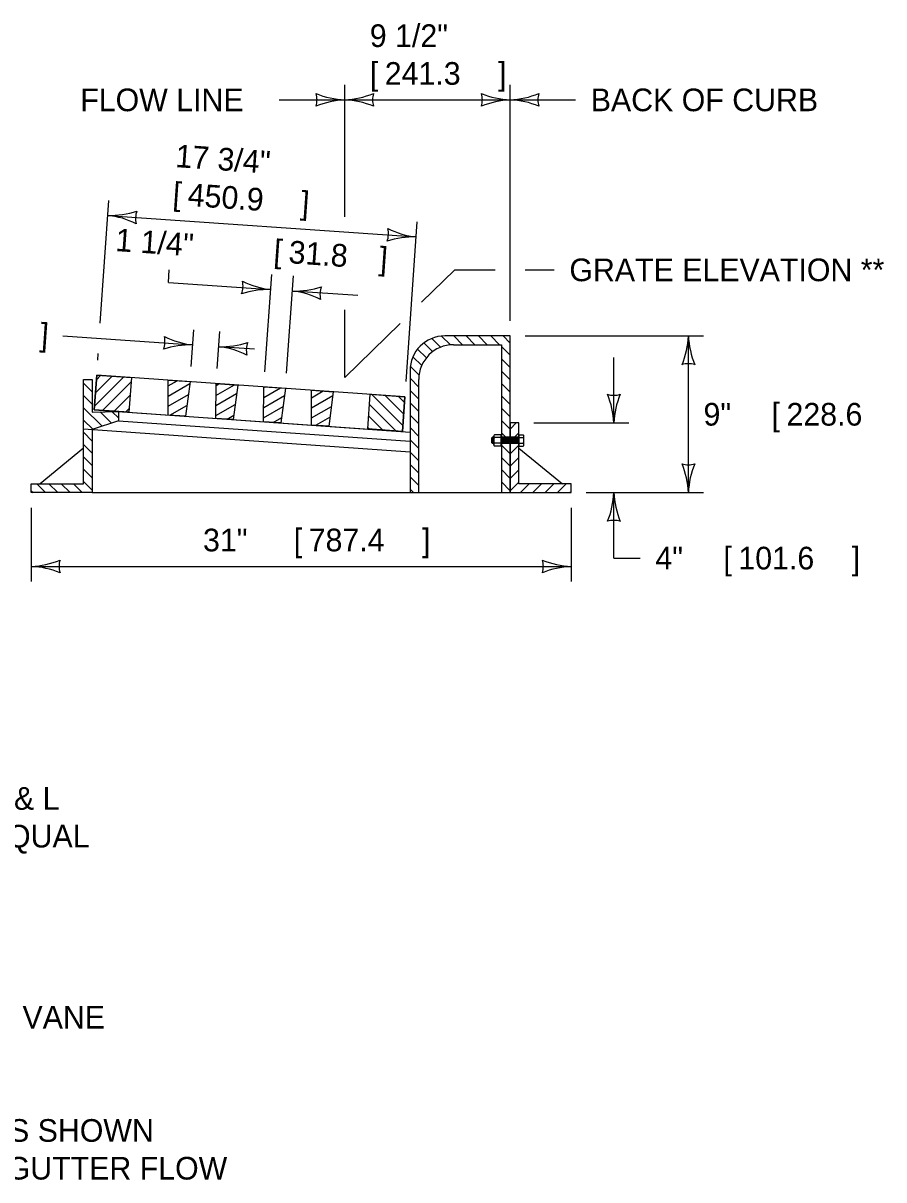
# Model space of a CAD drawing. Extents: x 49991.4 to 50057, y 49987.6 to 50011.4.
# Drawn here: x 50051.205 to 50053.484, y 49989.217 to 49992.28 of the extents above; entities that cross this region are included whole.
import ezdxf

# ---------------------------------------------------------------- set-up
doc = ezdxf.new("R2010")
doc.units = 0
for name, color, linetype in [('Level 1', 7, 'Continuous'), ('Level 2', 7, 'Continuous'), ('Level 3', 7, 'Continuous'), ('Level 4', 7, 'Continuous')]:
    doc.layers.add(name, color=color, linetype=linetype)

msp = doc.modelspace()

# ---------------------------------------------------------------- linework, layer by layer
at = {"layer": 'Level 1'}
for p, q in [((50052.2662, 49991.4332), (50052.2892, 49991.4101)), ((50052.287, 49991.4449), (50052.31, 49991.4219)), ((50052.3132, 49991.4513), (50052.3363, 49991.4282)), ((50052.3454, 49991.4517), (50052.3685, 49991.4286)), ((50052.378, 49991.4517), (50052.4011, 49991.4286)), ((50052.4106, 49991.4517), (50052.4337, 49991.4286)), ((50052.4432, 49991.4517), (50052.4663, 49991.4286)), ((50052.4714, 49991.4235), (50052.4945, 49991.4004)), ((50052.4758, 49991.4517), (50052.4945, 49991.433)), ((50052.2373, 49991.3968), (50052.2604, 49991.3738)), ((50052.2496, 49991.4171), (50052.2727, 49991.3941)), ((50052.2302, 49991.3714), (50052.2532, 49991.3483)), ((50052.4714, 49991.3909), (50052.4945, 49991.3678)), ((50051.4, 49991.348), (50051.3935, 49991.256)), ((50051.3942, 49991.2657), (50051.4715, 49991.343)), ((50051.3967, 49991.3008), (50051.441, 49991.3451)), ((50051.3991, 49991.3358), (50051.4105, 49991.3472)), ((50052.2161, 49991.2909), (50051.4, 49991.348)), ((50051.5895, 49991.3193), (50051.6134, 49991.333)), ((50052.2294, 49991.3395), (50052.2525, 49991.3165)), ((50052.4714, 49991.3583), (50052.4945, 49991.3353)), ((50051.3652, 49991.3269), (50051.3882, 49991.3039)), ((50051.4155, 49991.2544), (50051.4911, 49991.33)), ((50051.5893, 49991.2925), (50051.6464, 49991.3255)), ((50051.7158, 49991.2942), (50051.7648, 49991.3224)), ((50051.716, 49991.3209), (50051.7237, 49991.3253)), ((50051.8423, 49991.2885), (50051.8864, 49991.3139)), ((50051.8425, 49991.3152), (50051.8452, 49991.3168)), ((50051.9688, 49991.288), (50051.9999, 49991.306)), ((50052.2294, 49991.307), (50052.2525, 49991.2839)), ((50052.4714, 49991.3257), (50052.4945, 49991.3027)), ((50051.3652, 49991.2943), (50051.3882, 49991.2713)), ((50051.446, 49991.2523), (50051.4887, 49991.295)), ((50051.5891, 49991.2658), (50051.6426, 49991.2967)), ((50051.7154, 49991.2407), (50051.7667, 49991.2703)), ((50051.7156, 49991.2675), (50051.7705, 49991.2992)), ((50051.8421, 49991.2618), (50051.8974, 49991.2937)), ((50051.9686, 49991.2613), (50052.0251, 49991.2939)), ((50052.1222, 49991.2701), (50052.1922, 49991.2001)), ((50052.1278, 49991.2971), (50052.2107, 49991.2142)), ((50052.1629, 49991.2946), (50052.2129, 49991.2446)), ((50052.1979, 49991.2922), (50052.215, 49991.2751)), ((50052.2097, 49991.1987), (50052.2161, 49991.2909)), ((50052.2294, 49991.2744), (50052.2525, 49991.2513)), ((50052.4714, 49991.2931), (50052.4945, 49991.2701)), ((50051.3652, 49991.2617), (50051.4143, 49991.2126)), ((50051.3935, 49991.256), (50052.2097, 49991.1989)), ((50051.4091, 49991.2504), (50051.4388, 49991.2208)), ((50051.4411, 49991.251), (50051.4574, 49991.2347)), ((50051.4574, 49991.2513), (50051.4574, 49991.2513)), ((50051.4574, 49991.2513), (50052.2294, 49991.1972)), ((50051.4764, 49991.2502), (50051.4862, 49991.2599)), ((50051.5939, 49991.242), (50051.6388, 49991.2679)), ((50051.7453, 49991.2314), (50051.7629, 49991.2415)), ((50051.8419, 49991.2351), (50051.8936, 49991.2649)), ((50051.9684, 49991.2346), (50052.0212, 49991.2651)), ((50052.1201, 49991.2396), (50052.1572, 49991.2025)), ((50052.2294, 49991.2418), (50052.2525, 49991.2187)), ((50052.4714, 49991.2605), (50052.4945, 49991.2375)), ((50051.3652, 49991.2291), (50051.3899, 49991.2045)), ((50051.4574, 49991.227), (50052.2294, 49991.173)), ((50051.5136, 49991.2229), (50051.5136, 49991.2229)), ((50051.8669, 49991.2229), (50051.8898, 49991.2361)), ((50051.9805, 49991.215), (50052.0174, 49991.2363)), ((50052.118, 49991.2091), (50052.1221, 49991.205)), ((50052.2294, 49991.2092), (50052.2522, 49991.1864)), ((50052.4714, 49991.2279), (50052.4945, 49991.2049)), ((50052.4945, 49991.2048), (50052.5108, 49991.2212)), ((50051.3652, 49991.2055), (50052.2294, 49991.1451)), ((50051.3652, 49991.1966), (50051.3882, 49991.1735)), ((50052.4452, 49991.1809), (50052.4481, 49991.1838)), ((50052.4452, 49991.1809), (50052.4452, 49991.1694)), ((50052.4466, 49991.1809), (50052.4466, 49991.1694)), ((50052.4481, 49991.1838), (50052.4481, 49991.1665)), ((50052.4509, 49991.1838), (50052.4481, 49991.1838)), ((50052.4495, 49991.1809), (50052.4495, 49991.1694)), ((50052.4509, 49991.1639), (50052.4509, 49991.1863)), ((50052.4509, 49991.1838), (50052.4509, 49991.1665)), ((50052.4707, 49991.1901), (50052.4529, 49991.1901)), ((50052.4707, 49991.1826), (50052.4529, 49991.1826)), ((50052.4707, 49991.1602), (50052.4707, 49991.1901)), ((50052.4714, 49991.1881), (50052.4707, 49991.1881)), ((50052.4714, 49991.1953), (50052.4945, 49991.1723)), ((50052.4714, 49991.1622), (50052.4714, 49991.1881)), ((50052.4945, 49991.1722), (50052.5175, 49991.1953)), ((50052.5175, 49991.1622), (50052.5175, 49991.1881)), ((50052.5175, 49991.1881), (50052.5182, 49991.1881)), ((50052.5182, 49991.1901), (50052.5291, 49991.1901)), ((50052.5182, 49991.1602), (50052.5182, 49991.1901)), ((50052.5182, 49991.1826), (50052.5291, 49991.1826)), ((50052.5311, 49991.1639), (50052.5311, 49991.1863)), ((50051.3652, 49991.1544), (50051.25, 49991.0599)), ((50051.3652, 49991.164), (50051.3882, 49991.1409)), ((50052.2294, 49991.1766), (50052.2525, 49991.1535)), ((50052.4452, 49991.1694), (50052.4481, 49991.1665)), ((50052.4509, 49991.1665), (50052.4481, 49991.1665)), ((50052.4707, 49991.1676), (50052.4529, 49991.1676)), ((50052.4707, 49991.1602), (50052.4529, 49991.1602)), ((50052.4714, 49991.1622), (50052.4707, 49991.1622)), ((50052.4714, 49991.1627), (50052.4945, 49991.1397)), ((50052.4945, 49991.1396), (50052.5175, 49991.1627)), ((50052.5175, 49991.1622), (50052.5182, 49991.1622)), ((50052.5175, 49991.1544), (50052.6327, 49991.0599)), ((50052.5182, 49991.1676), (50052.5291, 49991.1676)), ((50052.5182, 49991.1602), (50052.5291, 49991.1602)), ((50051.3652, 49991.1314), (50051.3882, 49991.1083)), ((50052.2294, 49991.144), (50052.2525, 49991.1209)), ((50052.4714, 49991.1302), (50052.4945, 49991.1071)), ((50052.4945, 49991.107), (50052.5175, 49991.1301)), ((50051.3652, 49991.0988), (50051.3882, 49991.0757)), ((50052.2294, 49991.1114), (50052.2525, 49991.0884)), ((50052.4714, 49991.0976), (50052.4945, 49991.0745)), ((50052.4945, 49991.0744), (50052.5175, 49991.0975)), ((50051.2411, 49991.0599), (50051.2642, 49991.0368)), ((50051.2737, 49991.0599), (50051.2968, 49991.0368)), ((50051.3063, 49991.0599), (50051.3294, 49991.0368)), ((50051.3389, 49991.0599), (50051.3619, 49991.0368)), ((50051.3652, 49991.0662), (50051.3882, 49991.0431)), ((50052.2294, 49991.0788), (50052.2525, 49991.0558)), ((50052.4714, 49991.065), (50052.4945, 49991.0419)), ((50052.4945, 49991.0419), (50052.5175, 49991.0649)), ((50052.522, 49991.0368), (50052.5451, 49991.0599)), ((50052.5546, 49991.0368), (50052.5777, 49991.0599)), ((50052.5872, 49991.0368), (50052.6103, 49991.0599)), ((50052.6198, 49991.0368), (50052.6429, 49991.0599)), ((50051.2269, 49991.0415), (50051.2316, 49991.0368)), ((50051.3882, 49991.0368), (50052.4945, 49991.0368)), ((50052.2294, 49991.0462), (50052.2388, 49991.0368)), ((50052.6524, 49991.0368), (50052.6558, 49991.0402))]:
    msp.add_line(p, q, dxfattribs=at)
for points in [[(50052.4945, 49991.0368), (50052.4945, 49991.4517), (50052.3216, 49991.4517)], [(50052.3447, 49991.4286), (50052.4714, 49991.4286), (50052.4714, 49991.0368), (50052.4945, 49991.0368)], [(50052.2294, 49991.3595), (50052.2294, 49991.0368), (50052.2525, 49991.0368), (50052.2525, 49991.3364)]]:
    msp.add_lwpolyline(points, dxfattribs=at)
for points in [[(50051.3882, 49991.2039), (50051.3882, 49991.0368), (50051.2269, 49991.0368), (50051.2269, 49991.0599), (50051.3652, 49991.0599), (50051.3652, 49991.3364), (50051.3882, 49991.3364), (50051.3882, 49991.25), (50051.4574, 49991.2513), (50051.4574, 49991.227)], [(50051.4, 49991.348), (50051.4919, 49991.3415), (50051.4855, 49991.2495), (50051.3935, 49991.2559)], [(50051.5889, 49991.2423), (50051.5896, 49991.3347), (50051.6471, 49991.3307), (50051.6349, 49991.2391)], [(50051.7154, 49991.2335), (50051.7161, 49991.3259), (50051.7735, 49991.3218), (50051.7614, 49991.2303)], [(50051.7154, 49991.2335), (50051.7161, 49991.3259), (50051.7735, 49991.3218), (50051.7614, 49991.2303)], [(50051.8418, 49991.2246), (50051.8425, 49991.317), (50051.9, 49991.313), (50051.8878, 49991.2214)], [(50051.9683, 49991.2158), (50051.969, 49991.3082), (50052.0264, 49991.3041), (50052.0143, 49991.2126)], [(50051.9683, 49991.2158), (50051.969, 49991.3082), (50052.0264, 49991.3041), (50052.0143, 49991.2126)], [(50052.1241, 49991.2973), (50052.2161, 49991.2909), (50052.2097, 49991.1989), (50052.1177, 49991.2053)], [(50052.5175, 49991.0599), (50052.5175, 49991.2212), (50052.4945, 49991.2212), (50052.4945, 49991.0368), (50052.6558, 49991.0368), (50052.6558, 49991.0599)]]:
    msp.add_lwpolyline(points, close=True, dxfattribs=at)
for centre, radius, start, end in [((50052.3216, 49991.3595), 0.0922, 90, 180), ((50052.3447, 49991.3364), 0.0922, 90, 180), ((50052.4554, 49991.1863), 0.0045, 123.6844, 236.3156), ((50052.4659, 49991.1751), 0.015, 150.0207, 209.9793), ((50052.5266, 49991.1863), 0.0045, 303.6844, 56.3156), ((50052.5161, 49991.1751), 0.015, 330.0207, 29.9793), ((50052.4554, 49991.1639), 0.00449, 123.6376, 236.3624), ((50052.5266, 49991.1639), 0.00449, 303.6376, 56.3624)]:
    msp.add_arc(centre, radius, start, end, dxfattribs=at)
at = {"layer": 'Level 3'}
for p, q in [((50052.0567, 49991.7671), (50052.0567, 49992.1169)), ((50052.4945, 49991.4917), (50052.4945, 49992.1169)), ((50051.8832, 49992.0769), (50052.0567, 49992.0769)), ((50052.0567, 49992.0769), (50052.4945, 49992.0769)), ((50052.4945, 49992.0769), (50052.6679, 49992.0769)), ((50051.4096, 49991.4852), (50051.4323, 49991.8108)), ((50051.4295, 49991.7709), (50052.2457, 49991.7139)), ((50052.2189, 49991.3308), (50052.2485, 49991.7537)), ((50051.8453, 49991.3569), (50051.8633, 49991.6146)), ((50051.9028, 49991.3529), (50051.9208, 49991.6106)), ((50052.2602, 49991.541), (50052.3479, 49991.6267)), ((50052.3479, 49991.6267), (50052.4545, 49991.6267)), ((50052.5345, 49991.6267), (50052.6113, 49991.6267)), ((50051.5898, 49991.5936), (50051.8605, 49991.5747)), ((50052.091, 49991.5585), (50051.918, 49991.5706)), ((50052.0567, 49991.342), (50052.0567, 49991.5209)), ((50052.0567, 49991.342), (50052.203, 49991.4851)), ((50051.6499, 49991.3706), (50051.6567, 49991.4679)), ((50051.7189, 49991.3657), (50051.7257, 49991.4631)), ((50051.3103, 49991.4521), (50051.6539, 49991.428)), ((50051.8179, 49991.4166), (50051.7229, 49991.4232)), ((50052.5345, 49991.4517), (50053.0064, 49991.4517)), ((50052.9664, 49991.0368), (50052.9664, 49991.4517)), ((50051.4028, 49991.3879), (50051.404, 49991.4054)), ((50052.769, 49991.2212), (50052.769, 49991.3946)), ((50052.5575, 49991.2212), (50052.809, 49991.2212)), ((50052.6958, 49991.0368), (50053.0064, 49991.0368)), ((50052.769, 49990.8634), (50052.769, 49991.0368)), ((50051.2269, 49990.9968), (50051.2269, 49990.8013)), ((50052.6558, 49990.9968), (50052.6558, 49990.8013)), ((50051.2269, 49990.8413), (50052.6558, 49990.8413)), ((50052.769, 49990.8634), (50052.839, 49990.8634))]:
    msp.add_line(p, q, dxfattribs=at)
msp.add_lwpolyline([(50051.5898, 49991.5936), (50051.5898, 49991.5936), (50051.5921, 49991.6265)], dxfattribs=at)
for centre, radius, start, end in [((50052.0658, 49992.2991), 0.2223, 247.456, 267.6395), ((50051.9284, 49992.0769), 0.0548, 342.1388, 17.8612), ((50052.0681, 49991.8442), 0.233, 92.8273, 112.0772), ((50052.0452, 49992.3097), 0.233, 272.8273, 292.0772), ((50052.0475, 49991.8548), 0.2223, 67.456, 87.6395), ((50052.1849, 49992.0769), 0.0548, 162.1388, 197.8612), ((50052.5036, 49992.2991), 0.2223, 247.456, 267.6395), ((50052.3662, 49992.0769), 0.0548, 342.1388, 17.8612), ((50052.5059, 49991.8442), 0.233, 92.8273, 112.0772), ((50052.483, 49992.3097), 0.233, 272.8273, 292.0772), ((50052.4853, 49991.8548), 0.2223, 67.456, 87.6395), ((50052.6227, 49992.0769), 0.0548, 162.1388, 197.8612), ((50051.4343, 49992.0039), 0.233, 268.8273, 288.0772), ((50051.4049, 49991.55), 0.2223, 63.456, 83.6395), ((50051.5574, 49991.762), 0.0548, 158.1388, 193.8612), ((50052.1178, 49991.7228), 0.0548, 338.1388, 13.8612), ((50052.2703, 49991.9348), 0.2223, 243.456, 263.6395), ((50052.2409, 49991.4809), 0.233, 88.8273, 108.0772), ((50051.7326, 49991.5836), 0.0548, 338.1388, 13.8612), ((50051.8852, 49991.7956), 0.2223, 243.456, 263.6395), ((50051.9228, 49991.8036), 0.233, 268.8273, 288.0772), ((50052.0459, 49991.5617), 0.0548, 158.1388, 193.8612), ((50051.8558, 49991.3417), 0.233, 88.8273, 108.0772), ((50051.8934, 49991.3497), 0.2223, 63.456, 83.6395), ((50051.526, 49991.437), 0.0548, 338.1388, 13.8612), ((50051.6491, 49991.1951), 0.233, 88.8273, 108.0772), ((50051.6785, 49991.649), 0.2223, 243.456, 263.6395), ((50051.7277, 49991.6562), 0.233, 268.8273, 288.0772), ((50051.6983, 49991.2023), 0.2223, 63.456, 83.6395), ((50051.8508, 49991.4143), 0.0548, 158.1388, 193.8612), ((50052.7443, 49991.4608), 0.2223, 337.456, 357.6395), ((50053.1991, 49991.4632), 0.233, 182.8273, 202.0772), ((50052.9664, 49991.3235), 0.0548, 72.1388, 107.8612), ((50052.769, 49991.3494), 0.0548, 252.1388, 287.8612), ((50052.5363, 49991.2097), 0.233, 2.8273, 22.0772), ((50052.9912, 49991.2121), 0.2223, 157.456, 177.6395), ((50052.9664, 49991.1651), 0.0548, 252.1388, 287.8612), ((50052.7337, 49991.0253), 0.233, 2.8273, 22.0772), ((50053.1885, 49991.0277), 0.2223, 157.456, 177.6395), ((50052.5469, 49991.046), 0.2223, 337.456, 357.6395), ((50053.0018, 49991.0483), 0.233, 182.8273, 202.0772), ((50052.769, 49990.9086), 0.0548, 72.1388, 107.8612), ((50051.2154, 49991.074), 0.233, 272.8273, 292.0772), ((50051.2178, 49990.6192), 0.2223, 67.456, 87.6395), ((50051.3551, 49990.8413), 0.0548, 162.1388, 197.8612), ((50052.6649, 49991.0635), 0.2223, 247.456, 267.6395), ((50052.5276, 49990.8413), 0.0548, 342.1388, 17.8612), ((50052.6673, 49990.6086), 0.233, 92.8273, 112.0772)]:
    msp.add_arc(centre, radius, start, end, dxfattribs=at)
at = {"layer": 'Level 4'}
for p, q in [((50052.5175, 49991.1838), (50052.4714, 49991.1838)), ((50052.4725, 49991.1809), (50052.4725, 49991.1694)), ((50052.474, 49991.1838), (50052.474, 49991.1665)), ((50052.4754, 49991.1809), (50052.4754, 49991.1694)), ((50052.4769, 49991.1838), (50052.4769, 49991.1665)), ((50052.4783, 49991.1809), (50052.4783, 49991.1694)), ((50052.4797, 49991.1838), (50052.4797, 49991.1665)), ((50052.4812, 49991.1809), (50052.4812, 49991.1694)), ((50052.4826, 49991.1838), (50052.4826, 49991.1665)), ((50052.4841, 49991.1809), (50052.4841, 49991.1694)), ((50052.4855, 49991.1838), (50052.4855, 49991.1665)), ((50052.4869, 49991.1809), (50052.4869, 49991.1694)), ((50052.4884, 49991.1838), (50052.4884, 49991.1665)), ((50052.4898, 49991.1809), (50052.4898, 49991.1694)), ((50052.4913, 49991.1838), (50052.4913, 49991.1665)), ((50052.4927, 49991.1809), (50052.4927, 49991.1694)), ((50052.4941, 49991.1838), (50052.4941, 49991.1665)), ((50052.4956, 49991.1809), (50052.4956, 49991.1694)), ((50052.497, 49991.1838), (50052.497, 49991.1665)), ((50052.4985, 49991.1809), (50052.4985, 49991.1694)), ((50052.4999, 49991.1838), (50052.4999, 49991.1665)), ((50052.5013, 49991.1809), (50052.5013, 49991.1694)), ((50052.5028, 49991.1838), (50052.5028, 49991.1665)), ((50052.5042, 49991.1809), (50052.5042, 49991.1694)), ((50052.5057, 49991.1838), (50052.5057, 49991.1665)), ((50052.5071, 49991.1809), (50052.5071, 49991.1694)), ((50052.5085, 49991.1838), (50052.5085, 49991.1665)), ((50052.51, 49991.1809), (50052.51, 49991.1694)), ((50052.5114, 49991.1838), (50052.5114, 49991.1665)), ((50052.5129, 49991.1809), (50052.5129, 49991.1694)), ((50052.5143, 49991.1838), (50052.5143, 49991.1665)), ((50052.5157, 49991.1809), (50052.5157, 49991.1694)), ((50052.5175, 49991.1665), (50052.4714, 49991.1665))]:
    msp.add_line(p, q, dxfattribs=at)

# ---------------------------------------------------------------- texts
at = {"layer": 'Level 2'}
for s, rotation, p in [('9 1/2"', 0, (50052.123, 49992.2169)), ('[', 0, (50052.123, 49992.1169)), ('241.3', 0, (50052.1626, 49992.1169)), (']', 0, (50052.4626, 49992.1169)), ('FLOW LINE', 0, (50051.3564, 49992.0469)), ('BACK OF CURB', 0, (50052.7079, 49992.0469)), ('17 3/4"', 356, (50051.6069, 49991.899)), ('[', 356, (50051.5999, 49991.7992)), ('450.9', 356, (50051.6395, 49991.7964)), (']', 356, (50051.9388, 49991.7755)), ('1 1/4" ', 356, (50051.4481, 49991.6767)), ('[', 356, (50051.867, 49991.6474)), ('31.8', 356, (50051.9066, 49991.6447)), (']', 356, (50052.146, 49991.6279)), ('GRATE ELEVATION **', 360, (50052.6513, 49991.5967)), (']', 356, (50051.2485, 49991.4262)), ('9" ', 360, (50053.0064, 49991.2143)), ('[', 360, (50053.1864, 49991.2143)), ('228.6', 360, (50053.2261, 49991.2143)), ('4" ', 360, (50052.879, 49990.8334)), ('[', 360, (50053.059, 49990.8334)), ('101.6', 360, (50053.0987, 49990.8334)), (']', 360, (50053.3987, 49990.8334))]:
    msp.add_text(s, height=0.06, rotation=rotation, dxfattribs=at).set_placement(p)
for s, p in [('31" ', (50051.6815, 49990.8813)), ('[', (50051.9215, 49990.8813)), ('787.4', (50051.9612, 49990.8813)), (']', (50052.2612, 49990.8813)), ('NOTE: NEENAH FOUNDRY R-3067-R (SHOWN), D & L', (50049.2821, 49990.197)), ('      FOUNDRY I-3519 TYPE "DL" OR APPROVED EQUAL', (50049.2821, 49990.097)), (' # PROVIDE TYPE B CURB INLETS WITH CURVED VANE', (50049.2821, 49989.6176)), ('** GRATE ELEVATIONS FOR TYPE B CURB INLETS SHOWN', (50049.2821, 49989.3176)), (' LESS THAN GUTTER FLOW', (50050.6713, 49989.2176))]:
    msp.add_text(s, height=0.06, dxfattribs=at).set_placement(p)

doc.saveas('drawing.dxf')
